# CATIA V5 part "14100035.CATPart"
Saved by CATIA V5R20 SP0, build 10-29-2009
Part number: 14100035
Definition: NONE
Nomenclature: 14100035
Source: Unknown
Description: 14100035
Bounding box of the stored display mesh (mm): x -17.5 to 70, y -64 to 53.915, z -54.1 to 54.1
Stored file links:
  C:\Users\Utente\Desktop\IO LAVORO\3D X SITO CF\X SITO\PLASTICA\RF2\14100035.CATPart
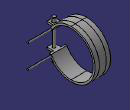
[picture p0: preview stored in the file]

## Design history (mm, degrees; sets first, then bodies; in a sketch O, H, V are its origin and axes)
Body1 "14100035" (main body)
  Solid1: solid without history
